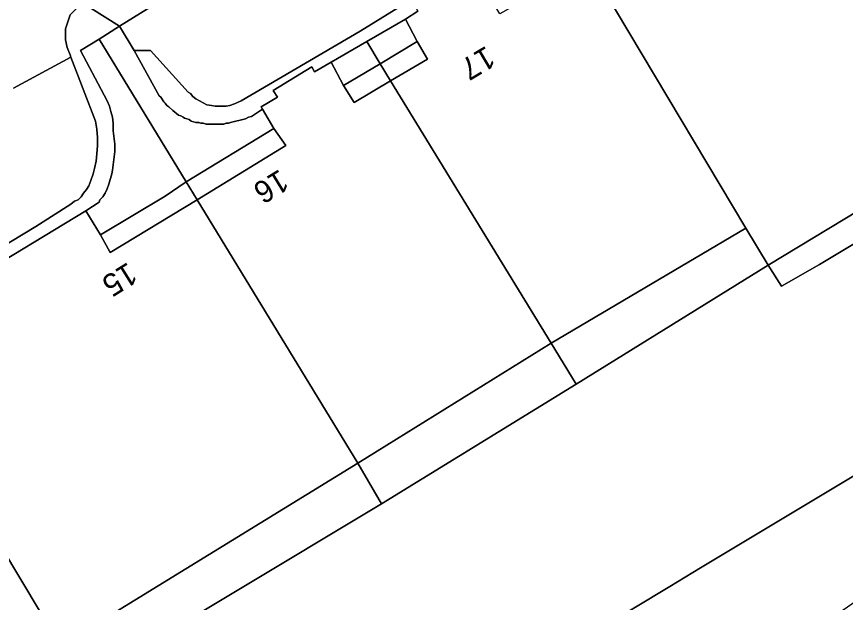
# Model space of a CAD drawing. Extents: x 529240 to 530363, y 179600 to 180767.
# Drawn here: x 529829.9 to 529885.7, y 180267.7 to 180307.1 of the extents above; entities that cross this region are included whole.
import ezdxf

# ---------------------------------------------------------------- set-up
doc = ezdxf.new("R2010")
doc.units = 0
for name, color, linetype in [('Building', 7, 'Continuous'), ('General surface', 7, 'Continuous'), ('Road Or Track', 7, 'Continuous'), ('Roadside', 7, 'Continuous'), ('Unclassified', 7, 'Continuous')]:
    doc.layers.add(name, color=color, linetype=linetype)

msp = doc.modelspace()

# ---------------------------------------------------------------- linework, layer by layer
at = {"layer": 'Building'}
for points in [[(529872.55, 180321.4), (529873.2, 180320.15), (529865.55, 180315.5), (529867.6, 180312), (529868.4, 180310.65), (529868.5, 180310.5), (529879, 180292.9), (529880.5, 180290.4), (529897.8, 180300.85), (529896.7, 180302.7), (529898.5, 180303.95), (529898.35, 180304.2), (529885.1, 180327), (529877.8, 180322.9), (529877.2, 180324), (529876.05, 180325.7), (529871.65, 180322.85)], [(529856.9, 180305.45), (529857.6, 180304.25), (529855.1, 180302.8), (529865.9, 180285.15), (529879, 180292.9), (529868.5, 180310.5), (529868.4, 180310.65), (529862.45, 180307.3), (529861.8, 180308.4), (529860.94, 180309.98), (529859.6, 180309.2), (529859.4, 180309.5), (529856.75, 180307.85), (529856.95, 180307.5), (529856.1, 180306.95)], [(529855.1, 180302.8), (529857.6, 180304.25), (529856.9, 180305.45), (529854.4, 180303.95)], [(529865.9, 180285.15), (529855.1, 180302.8), (529852.65, 180301.35), (529851.95, 180302.5), (529851.1, 180304.05), (529850, 180303.4), (529849.8, 180303.75), (529847.2, 180302.15), (529847.5, 180301.7), (529846.4, 180301.05), (529846.5, 180300.9), (529847.25, 180299.6), (529848.05, 180298.45), (529842.1, 180294.8), (529852.9, 180277.1)], [(529855.1, 180302.8), (529854.4, 180303.95), (529851.95, 180302.5), (529852.65, 180301.35)], [(529842.1, 180294.8), (529848.05, 180298.45), (529847.25, 180299.6), (529841.35, 180296)], [(529842.1, 180294.8), (529841.35, 180296), (529839.95, 180295.05), (529835.6, 180292.45), (529836.25, 180291.25)], [(529852.9, 180277.1), (529842.1, 180294.8), (529836.25, 180291.25), (529835.6, 180292.45), (529834.6, 180294.05), (529826.9, 180289.4), (529827.65, 180288.2), (529827.9, 180287.75), (529828.6, 180286.6), (529822.2, 180282.65), (529832.9, 180264.8)], [(529865.9, 180285.15), (529867.6, 180282.4), (529880.5, 180290.4), (529879, 180292.9)], [(529852.9, 180277.1), (529854.5, 180274.35), (529867.6, 180282.4), (529865.9, 180285.15)], [(529832.9, 180264.8), (529822.2, 180282.65), (529816.2, 180278.95), (529815.5, 180280.15), (529815.25, 180280.55), (529814.45, 180281.85), (529810.5, 180279.4), (529823.05, 180258.85)], [(529834.4, 180262.3), (529854.5, 180274.35), (529852.9, 180277.1), (529832.9, 180264.8)]]:
    msp.add_lwpolyline(points, close=True, dxfattribs=at)
for points in [[(529879, 180292.9), (529868.5, 180310.5), (529868.4, 180310.65)], [(529856.1, 180306.95), (529856.95, 180307.5), (529856.75, 180307.85), (529859.4, 180309.5), (529859.6, 180309.2), (529860.94, 180309.98)], [(529856.9, 180305.45), (529856.1, 180306.95)], [(529853.5, 180305.45), (529854.4, 180303.95)], [(529854.4, 180303.95), (529856.9, 180305.45)], [(529855.1, 180302.8), (529857.6, 180304.25), (529856.9, 180305.45)], [(529846.5, 180300.9), (529846.4, 180301.05), (529847.5, 180301.7), (529847.2, 180302.15), (529849.8, 180303.75), (529850, 180303.4), (529851.1, 180304.05)], [(529851.1, 180304.05), (529851.95, 180302.5)], [(529851.95, 180302.5), (529854.4, 180303.95)], [(529854.4, 180303.95), (529855.1, 180302.8)], [(529898.35, 180304.2), (529898.5, 180303.95), (529896.7, 180302.7), (529897.8, 180300.85), (529880.5, 180290.4)], [(529851.95, 180302.5), (529852.65, 180301.35), (529855.1, 180302.8)], [(529855.1, 180302.8), (529865.9, 180285.15)], [(529847.25, 180299.6), (529846.5, 180300.9)], [(529841.35, 180296), (529847.25, 180299.6)], [(529842.1, 180294.8), (529848.05, 180298.45), (529847.25, 180299.6)], [(529835.6, 180292.45), (529839.95, 180295.05), (529841.35, 180296)], [(529841.35, 180296), (529842.1, 180294.8)], [(529835.6, 180292.45), (529836.25, 180291.25), (529842.1, 180294.8)], [(529842.1, 180294.8), (529852.9, 180277.1)], [(529826.9, 180289.4), (529834.6, 180294.05)], [(529834.6, 180294.05), (529835.6, 180292.45)], [(529879, 180292.9), (529865.9, 180285.15)], [(529880.5, 180290.4), (529879, 180292.9)], [(529880.5, 180290.4), (529867.6, 180282.4)], [(529865.9, 180285.15), (529852.9, 180277.1)], [(529865.9, 180285.15), (529867.6, 180282.4)], [(529832.9, 180264.8), (529822.2, 180282.65)], [(529867.6, 180282.4), (529854.5, 180274.35)], [(529852.9, 180277.1), (529832.9, 180264.8)], [(529852.9, 180277.1), (529854.5, 180274.35)], [(529854.5, 180274.35), (529834.4, 180262.3)]]:
    msp.add_lwpolyline(points, dxfattribs=at)
at = {"layer": 'General surface'}
for points in [[(529839.7, 180308.25), (529836.87, 180306.48), (529837.85, 180304.85), (529838.95, 180304.85), (529841.5, 180302.05), (529841.65, 180301.95), (529841.8, 180301.75), (529842, 180301.6), (529842.25, 180301.45), (529842.75, 180301.2), (529843.05, 180301.15), (529843.3, 180301.1), (529844.05, 180301.1), (529844.3, 180301.15), (529844.6, 180301.25), (529844.8, 180301.35), (529845.05, 180301.45), (529853.05, 180306.15), (529859.85, 180310.35)], [(529807.6, 180278.7), (529831.25, 180293), (529833.6, 180294.5), (529833.85, 180294.7), (529834.1, 180294.8), (529834.3, 180295), (529834.45, 180295.25), (529834.65, 180295.5), (529834.8, 180295.75), (529834.95, 180296.1), (529835.1, 180296.55), (529835.2, 180296.9), (529835.3, 180297.4), (529835.35, 180297.9), (529835.4, 180298.45), (529835.4, 180299), (529835.35, 180299.55), (529835.25, 180300.1), (529833.6, 180304.4), (529829.75, 180302.3)], [(529869.15, 180265.95), (529873.9, 180268.8), (529875.43, 180269.73), (529875.95, 180270.05), (529905.7, 180287.9), (529908.15, 180289.4), (529903.9, 180296.85), (529901.25, 180295.25), (529900.7, 180296.2), (529899.55, 180295.5), (529898.35, 180297.5), (529897.55, 180297.05), (529896.9, 180298.2), (529883.95, 180290.45), (529881.4, 180289), (529880.5, 180290.4), (529867.6, 180282.4), (529854.5, 180274.35), (529834.4, 180262.3)], [(529800.7, 180208.5), (529904.3, 180280.2), (529902.1, 180283.55), (529905.15, 180285.5), (529906.55, 180286.5), (529905.7, 180287.9), (529875.95, 180270.05), (529875.43, 180269.73), (529873.9, 180268.8), (529869.15, 180265.95)]]:
    msp.add_lwpolyline(points, dxfattribs=at)
for points in [[(529856.1, 180306.95), (529853.5, 180305.45), (529854.4, 180303.95), (529856.9, 180305.45)], [(529847.25, 180299.6), (529846.5, 180300.9), (529845.75, 180300.4), (529845.55, 180300.35), (529845.35, 180300.25), (529844.35, 180300), (529844.2, 180299.95), (529844.05, 180299.95), (529843.9, 180299.9), (529842.7, 180299.9), (529842.5, 180299.95), (529842.35, 180299.95), (529842.2, 180300), (529842, 180300), (529841.7, 180300.1), (529841.55, 180300.2), (529841.25, 180300.3), (529841.15, 180300.35), (529841, 180300.45), (529840.85, 180300.5), (529840.7, 180300.6), (529840.6, 180300.7), (529840.45, 180300.8), (529840.2, 180301.05), (529840.05, 180301.15), (529839.95, 180301.3), (529839.85, 180301.4), (529839.65, 180301.7), (529839.55, 180301.8), (529837.85, 180304.85), (529836.87, 180306.48), (529835.5, 180305.6), (529841.35, 180296)], [(529834.6, 180294.05), (529835.6, 180292.45), (529839.95, 180295.05), (529841.35, 180296), (529835.5, 180305.6), (529834.25, 180304.85), (529835.85, 180301.85), (529836.05, 180301.45), (529836.2, 180301.1), (529836.3, 180300.75), (529836.4, 180300.35), (529836.45, 180299.95), (529836.45, 180299.45), (529836.55, 180298.55), (529836.55, 180298.05), (529836.45, 180297.15), (529836.4, 180296.8), (529836.35, 180296.55), (529836.15, 180295.85), (529836.05, 180295.55), (529835.9, 180295.25), (529835.75, 180295), (529835.55, 180294.8), (529835.5, 180294.65)], [(529851.95, 180302.5), (529854.4, 180303.95), (529853.5, 180305.45), (529851.1, 180304.05)], [(529898.75, 180299.35), (529900.7, 180296.2), (529901.25, 180295.25), (529903.9, 180296.85), (529899.4, 180304.85), (529898.35, 180304.2), (529898.5, 180303.95), (529896.7, 180302.7), (529897.8, 180300.85), (529880.5, 180290.4), (529881.4, 180289), (529883.95, 180290.45), (529896.9, 180298.2)]]:
    msp.add_lwpolyline(points, close=True, dxfattribs=at)
at = {"layer": 'Road Or Track'}
for points in [[(529836.87, 180306.48), (529834.95, 180307.7), (529834.65, 180307.85), (529834.35, 180307.85), (529833.95, 180307.65), (529833.55, 180307.25), (529833.3, 180306.5), (529833.25, 180306.3), (529833.25, 180305.55), (529833.35, 180305.05), (529833.55, 180304.55), (529833.6, 180304.4)], [(529834.95, 180307.7), (529836.87, 180306.48), (529839.7, 180308.25)], [(529829.75, 180302.3), (529833.6, 180304.4), (529833.55, 180304.55), (529833.35, 180305.05), (529833.25, 180305.55), (529833.25, 180306.3), (529833.3, 180306.5), (529833.55, 180307.25)]]:
    msp.add_lwpolyline(points, dxfattribs=at)
at = {"layer": 'Roadside'}
for points in [[(529859.85, 180310.35), (529853.05, 180306.15), (529845.05, 180301.45), (529844.8, 180301.35), (529844.6, 180301.25), (529844.3, 180301.15), (529844.05, 180301.1), (529843.3, 180301.1), (529843.05, 180301.15), (529842.75, 180301.2), (529842.25, 180301.45), (529842, 180301.6), (529841.8, 180301.75), (529841.65, 180301.95), (529841.5, 180302.05), (529838.95, 180304.85), (529837.85, 180304.85), (529839.55, 180301.8), (529839.65, 180301.7), (529839.85, 180301.4), (529839.95, 180301.3), (529840.05, 180301.15), (529840.2, 180301.05), (529840.45, 180300.8), (529840.6, 180300.7), (529840.7, 180300.6), (529840.85, 180300.5), (529841, 180300.45), (529841.15, 180300.35), (529841.25, 180300.3), (529841.55, 180300.2), (529841.7, 180300.1), (529842, 180300), (529842.2, 180300), (529842.35, 180299.95), (529842.5, 180299.95), (529842.7, 180299.9), (529843.9, 180299.9), (529844.05, 180299.95), (529844.2, 180299.95), (529844.35, 180300), (529845.35, 180300.25), (529845.55, 180300.35), (529845.75, 180300.4), (529846.5, 180300.9), (529846.4, 180301.05), (529847.5, 180301.7), (529847.2, 180302.15), (529849.8, 180303.75), (529850, 180303.4), (529851.1, 180304.05), (529853.5, 180305.45), (529856.1, 180306.95), (529856.95, 180307.5)], [(529833.55, 180307.25), (529833.3, 180306.5), (529833.25, 180306.3), (529833.25, 180305.55), (529833.35, 180305.05), (529833.55, 180304.55), (529833.6, 180304.4), (529835.25, 180300.1), (529835.35, 180299.55), (529835.4, 180299), (529835.4, 180298.45), (529835.35, 180297.9), (529835.3, 180297.4), (529835.2, 180296.9), (529835.1, 180296.55), (529834.95, 180296.1), (529834.8, 180295.75), (529834.65, 180295.5), (529834.45, 180295.25), (529834.3, 180295), (529834.1, 180294.8), (529833.85, 180294.7), (529833.6, 180294.5), (529831.25, 180293), (529807.6, 180278.7)], [(529826.9, 180289.4), (529834.6, 180294.05), (529835.5, 180294.65), (529835.55, 180294.8), (529835.75, 180295), (529835.9, 180295.25), (529836.05, 180295.55), (529836.15, 180295.85), (529836.35, 180296.55), (529836.4, 180296.8), (529836.45, 180297.15), (529836.55, 180298.05), (529836.55, 180298.55), (529836.45, 180299.45), (529836.45, 180299.95), (529836.4, 180300.35), (529836.3, 180300.75), (529836.2, 180301.1), (529836.05, 180301.45), (529835.85, 180301.85), (529834.25, 180304.85), (529835.5, 180305.6), (529836.87, 180306.48), (529834.95, 180307.7)]]:
    msp.add_lwpolyline(points, dxfattribs=at)
at = {"layer": 'Unclassified'}
for points in [[(529859.85, 180310.35), (529853.05, 180306.15), (529845.05, 180301.45), (529844.8, 180301.35), (529844.6, 180301.25), (529844.3, 180301.15), (529844.05, 180301.1), (529843.3, 180301.1), (529843.05, 180301.15), (529842.75, 180301.2), (529842.25, 180301.45), (529842, 180301.6), (529841.8, 180301.75), (529841.65, 180301.95), (529841.5, 180302.05), (529838.95, 180304.85), (529837.85, 180304.85)], [(529836.87, 180306.48), (529839.7, 180308.25)], [(529853.5, 180305.45), (529856.1, 180306.95)], [(529836.87, 180306.48), (529835.5, 180305.6)], [(529836.87, 180306.48), (529837.85, 180304.85)], [(529835.5, 180305.6), (529834.25, 180304.85)], [(529835.5, 180305.6), (529841.35, 180296)], [(529851.1, 180304.05), (529853.5, 180305.45)], [(529834.6, 180294.05), (529835.5, 180294.65), (529835.55, 180294.8), (529835.75, 180295), (529835.9, 180295.25), (529836.05, 180295.55), (529836.15, 180295.85), (529836.35, 180296.55), (529836.4, 180296.8), (529836.45, 180297.15), (529836.55, 180298.05), (529836.55, 180298.55), (529836.45, 180299.45), (529836.45, 180299.95), (529836.4, 180300.35), (529836.3, 180300.75), (529836.2, 180301.1), (529836.05, 180301.45), (529835.85, 180301.85), (529834.25, 180304.85)], [(529837.85, 180304.85), (529839.55, 180301.8), (529839.65, 180301.7), (529839.85, 180301.4), (529839.95, 180301.3), (529840.05, 180301.15), (529840.2, 180301.05), (529840.45, 180300.8), (529840.6, 180300.7), (529840.7, 180300.6), (529840.85, 180300.5), (529841, 180300.45), (529841.15, 180300.35), (529841.25, 180300.3), (529841.55, 180300.2), (529841.7, 180300.1), (529842, 180300), (529842.2, 180300), (529842.35, 180299.95), (529842.5, 180299.95), (529842.7, 180299.9), (529843.9, 180299.9), (529844.05, 180299.95), (529844.2, 180299.95), (529844.35, 180300), (529845.35, 180300.25), (529845.55, 180300.35), (529845.75, 180300.4), (529846.5, 180300.9)], [(529833.6, 180304.4), (529835.25, 180300.1), (529835.35, 180299.55), (529835.4, 180299), (529835.4, 180298.45), (529835.35, 180297.9), (529835.3, 180297.4), (529835.2, 180296.9), (529835.1, 180296.55), (529834.95, 180296.1), (529834.8, 180295.75), (529834.65, 180295.5), (529834.45, 180295.25), (529834.3, 180295), (529834.1, 180294.8), (529833.85, 180294.7), (529833.6, 180294.5), (529831.25, 180293), (529807.6, 180278.7)], [(529829.75, 180302.3), (529833.6, 180304.4)], [(529896.9, 180298.2), (529883.95, 180290.45), (529881.4, 180289), (529880.5, 180290.4)], [(529905.7, 180287.9), (529875.95, 180270.05), (529875.43, 180269.73), (529873.9, 180268.8), (529869.15, 180265.95), (529861.95, 180261.6), (529856.55, 180258.25), (529848.3, 180253.15), (529842.15, 180249.39), (529832.42, 180243.43), (529825.5, 180239.2), (529822.73, 180237.53), (529810.9, 180230.4), (529801.05, 180224.3)]]:
    msp.add_lwpolyline(points, dxfattribs=at)

# ---------------------------------------------------------------- texts
for s, rotation, p in [('17', 210.7, (529861.55, 180305.2)), ('16', 211.4, (529847.65, 180296.9)), ('15', 212, (529837.45, 180290.65))]:
    msp.add_text(s, height=1.5, rotation=rotation, dxfattribs=at).set_placement(p)

doc.saveas('drawing.dxf')
